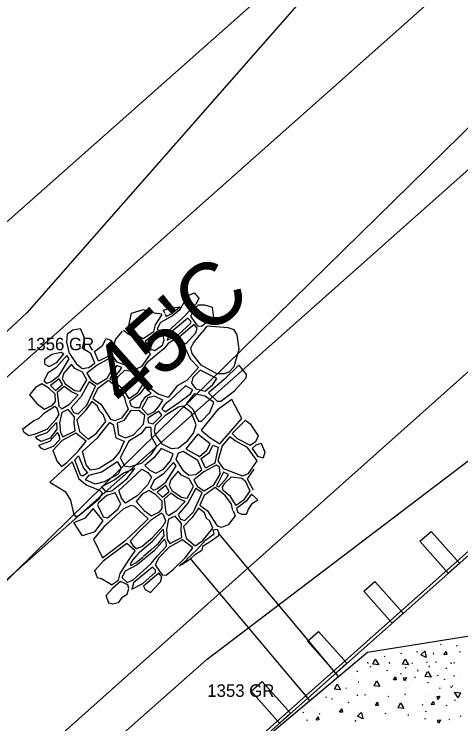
# Model space of a CAD drawing. Extents: x 49683 to 58852, y 49525 to 54803.
# Drawn here: x 53907.5 to 53943.1, y 51882.5 to 51939.1 of the extents above; entities that cross this region are included whole.
import ezdxf

# ---------------------------------------------------------------- set-up
doc = ezdxf.new("R2010")
doc.units = 0
for name, color, linetype in [('Level 1', 7, 'Continuous'), ('Level 11', 7, 'Continuous'), ('Level 16', 7, 'Continuous'), ('Level 18', 7, 'Continuous'), ('Level 27', 7, 'Continuous'), ('Level 3', 7, 'Continuous'), ('Level 48', 7, 'Continuous'), ('Level 57', 7, 'Continuous'), ('Level 7', 7, 'Continuous'), ('Level 8', 7, 'Continuous')]:
    doc.layers.add(name, color=color, linetype=linetype)

msp = doc.modelspace()

# ---------------------------------------------------------------- linework, layer by layer
at = {"layer": 'Level 1'}
msp.add_line((52544.807, 50683.302), (55534.583, 53340.862), dxfattribs=at)
at = {"layer": 'Level 11'}
msp.add_line((53894.91, 51911.927), (54324.203, 52292.615), dxfattribs=at)
at = {"layer": 'Level 16'}
for p, q in [((53922.709, 51897.172), (53923.403, 51897.677)), ((53923.325, 51897.993), (53923.656, 51898.041)), ((53923.403, 51897.677), (53923.325, 51897.993)), ((53923.656, 51898.041), (53923.782, 51897.709)), ((53923.782, 51897.709), (53923.735, 51897.472)), ((53922.014, 51896.397), (53922.709, 51897.172)), ((53923.277, 51897.172), (53922.882, 51896.903)), ((53923.735, 51897.472), (53923.277, 51897.172)), ((53922.488, 51896.65), (53922.409, 51896.334)), ((53922.882, 51896.903), (53922.488, 51896.65)), ((53921.225, 51895.639), (53922.014, 51896.397)), ((53921.84, 51895.97), (53921.351, 51895.544)), ((53922.409, 51896.334), (53921.84, 51895.97)), ((53920.609, 51895.117), (53921.272, 51895.623)), ((53921.351, 51895.544), (53920.861, 51895.212)), ((53921.272, 51895.623), (53921.225, 51895.639)), ((53920.861, 51895.212), (53920.609, 51895.117))]:
    msp.add_line(p, q, dxfattribs=at)
for points in [[(53920.663, 51915.527), (53921.297, 51916.644), (53921.805, 51916.891), (53922.188, 51916.466), (53921.968, 51915.993), (53920.907, 51914.878)], [(53919.463, 51915.272), (53919.414, 51915.368), (53919.357, 51915.487), (53919.785, 51915.644), (53920.688, 51915.777)], [(53919.463, 51915.243), (53919.525, 51915.115), (53919.574, 51914.993), (53919.979, 51915.201), (53920.688, 51915.777)], [(53920.649, 51915.752), (53920.58, 51915.692)], [(53922.152, 51915.935), (53921.818, 51915.582), (53921.515, 51915.034), (53921.872, 51914.52), (53922.084, 51914.241), (53922.397, 51914.219), (53922.734, 51914.491)], [(53922.152, 51915.935), (53922.639, 51915.912), (53923.236, 51915.727), (53923.335, 51915.11), (53923.376, 51914.761), (53923.165, 51914.529), (53922.734, 51914.491)], [(53916.531, 51913.893), (53916.806, 51915.251), (53917.767, 51915.561), (53918.262, 51915.334), (53919.236, 51915.208)], [(53916.531, 51913.893), (53917.759, 51913.251), (53918.605, 51913.803), (53918.74, 51914.33), (53919.256, 51915.166)], [(53920.663, 51915.527), (53920.089, 51915.042), (53919.133, 51914.527), (53918.875, 51914.024), (53919.291, 51913.632), (53919.769, 51913.841), (53920.907, 51914.878)], [(53911.864, 51912.039), (53911.674, 51912.978), (53911.719, 51913.601), (53912.149, 51913.935), (53912.737, 51914.029), (53913.058, 51913.271), (53912.88, 51912.467)], [(53922.489, 51913.783), (53922.845, 51914.23)], [(53924.393, 51910.513), (53924.597, 51910.588), (53925.009, 51911.007), (53925.398, 51912.39), (53925.238, 51913.545), (53924.997, 51913.943), (53924.52, 51914.087), (53922.845, 51914.23)], [(53916.074, 51913.829), (53915.541, 51913.187), (53915.185, 51911.998), (53915.613, 51911.374), (53917.156, 51910.812), (53917.634, 51910.996), (53918.333, 51911.99), (53917.563, 51913.055), (53916.559, 51913.593), (53916.187, 51913.876)], [(53924.393, 51910.513), (53924.214, 51910.427), (53923.626, 51910.427), (53922.367, 51911.118), (53921.654, 51912.041), (53921.539, 51912.492), (53921.771, 51912.933), (53922.473, 51913.768)], [(53920.982, 51912.658), (53920.442, 51913.07), (53920.087, 51913.057), (53919.731, 51912.849), (53919.388, 51912.407), (53918.039, 51911.303), (53917.523, 51910.567), (53918, 51909.672)], [(53911.864, 51912.039), (53912.403, 51911.248), (53912.88, 51910.844), (53913.419, 51910.918), (53913.897, 51911.274), (53913.58, 51912.033), (53912.88, 51912.467)], [(53921.008, 51912.632), (53921.496, 51911.61), (53922.146, 51910.939), (53921.243, 51909.909), (53920.455, 51909.457), (53919.729, 51908.543), (53918.932, 51908.794), (53918.449, 51909.171), (53918.026, 51909.646)], [(53909.896, 51911.196), (53909.897, 51911.601), (53910.461, 51911.997), (53911.207, 51912.149)], [(53909.896, 51911.196), (53910.256, 51911.009), (53910.868, 51911.325), (53911.434, 51912.022)], [(53911.207, 51912.149), (53911.434, 51912.022)], [(53924.191, 51909.973), (53925.358, 51911.106), (53925.948, 51910.362), (53925.923, 51910.069), (53925.029, 51909.06)], [(53908.684, 51908.742), (53909.309, 51908.027), (53909.889, 51907.604), (53910.526, 51907.928), (53910.761, 51908.208), (53910.74, 51908.789), (53910.238, 51909.291), (53909.679, 51909.626), (53909.154, 51909.346), (53908.684, 51908.742)], [(53916.383, 51908.049), (53916.283, 51908.544), (53915.782, 51909.242), (53914.974, 51909.878), (53914.103, 51909.228), (53913.747, 51908.456), (53914.371, 51908.003), (53915.134, 51906.813)], [(53924.191, 51909.973), (53922.963, 51908.904), (53923.655, 51908.254), (53923.949, 51908.254), (53925.029, 51909.06)], [(53910.078, 51905.997), (53910.816, 51906.811), (53911.04, 51907.191), (53910.895, 51907.649), (53910.694, 51907.828), (53909.811, 51907.235), (53909.448, 51906.89)], [(53916.398, 51908.022), (53916.56, 51907.616), (53916.022, 51906.889), (53915.484, 51906.688), (53915.161, 51906.784)], [(53910.078, 51905.997), (53909.064, 51905.575), (53908.631, 51905.491), (53908.248, 51905.781), (53908.147, 51906.03), (53909.002, 51906.664), (53909.448, 51906.89)], [(53924.849, 51905.67), (53925.892, 51906.732), (53926.271, 51906.43), (53926.922, 51905.469), (53926.688, 51905.003)], [(53910.092, 51905.74), (53910.838, 51906.543), (53910.871, 51906.018), (53910.325, 51905.303)], [(53910.325, 51905.303), (53909.605, 51905.031), (53909.339, 51905.178), (53909.158, 51905.41), (53910.092, 51905.74)], [(53910.584, 51904.628), (53911.104, 51905.181), (53911.071, 51905.482), (53910.926, 51905.739), (53910.303, 51905.048)], [(53911.242, 51903.031), (53911.65, 51903.36), (53912.578, 51904.266), (53913.205, 51905.049), (53912.378, 51905.696), (53911.294, 51905.103), (53910.547, 51904.314)], [(53924.849, 51905.67), (53925.242, 51905.277), (53926.27, 51904.739), (53926.708, 51905.025)], [(53910.584, 51904.628), (53909.874, 51904.359), (53909.608, 51904.506), (53909.426, 51904.738), (53910.303, 51905.048)], [(53926.755, 51904.751), (53926.429, 51904.482), (53926.87, 51903.87), (53927.315, 51903.734)], [(53926.755, 51904.751), (53927.157, 51904.882), (53927.438, 51904.183), (53927.315, 51903.734)], [(53910.547, 51904.314), (53910.882, 51903.436), (53911.242, 51903.031)], [(53912.079, 51903.394), (53910.308, 51901.775), (53911.528, 51901.045), (53911.943, 51900.353), (53912.184, 51899.292), (53912.36, 51899.052), (53912.636, 51899.124)], [(53912.079, 51903.394), (53912.623, 51902.058), (53913.244, 51901.542), (53914.255, 51901.143), (53914.466, 51900.932), (53914.244, 51900.416), (53912.636, 51899.124)], [(53926.569, 51902.818), (53926.035, 51902.056), (53926.511, 51901.161)], [(53924.894, 51899.538), (53924.795, 51900.033), (53924.293, 51900.731), (53923.485, 51901.367), (53922.615, 51900.717), (53922.259, 51899.944), (53922.883, 51899.492), (53923.645, 51898.302)], [(53916.412, 51897.203), (53917.103, 51897.839), (53918.143, 51898.857), (53917.072, 51899.839), (53916.759, 51899.928), (53916.156, 51899.637), (53915.017, 51898.597)], [(53913.883, 51897.836), (53914.553, 51898.691), (53913.757, 51899.697), (53913.108, 51898.916)], [(53924.909, 51899.511), (53925.072, 51899.105), (53924.533, 51898.377), (53923.996, 51898.176), (53923.672, 51898.273)], [(53913.883, 51897.836), (53912.915, 51897.5), (53912.222, 51898.58), (53913.108, 51898.916)], [(53915, 51898.581), (53914.628, 51898.262), (53913.794, 51897.232), (53914.503, 51895.762), (53916.394, 51897.186)], [(53917.442, 51896.191), (53918.477, 51897.092), (53919.349, 51898.032), (53919.382, 51897.507), (53918.879, 51896.847), (53918.353, 51896.366), (53917.763, 51895.851)], [(53918.354, 51895.28), (53918.9, 51895.909), (53919.616, 51896.669), (53919.583, 51896.971), (53919.438, 51897.227), (53918.621, 51896.322), (53917.898, 51895.735)], [(53915.213, 51893.588), (53915.788, 51893.963), (53915.923, 51894.49), (53916.672, 51895.703), (53917.101, 51896.304), (53916.44, 51896.892), (53914.545, 51895.478)], [(53917.417, 51896.166), (53916.904, 51895.569), (53916.708, 51895.275), (53916.757, 51895.152), (53917.161, 51895.361), (53917.744, 51895.834)], [(53915.213, 51893.588), (53914.421, 51894.081), (53914.118, 51894.153), (53913.895, 51894.75), (53914.545, 51895.478)], [(53917.873, 51895.71), (53917.271, 51895.202), (53916.315, 51894.686), (53916.057, 51894.183), (53916.473, 51893.792), (53916.951, 51894.001), (53918.328, 51895.255)], [(53918.335, 51892.985), (53919.12, 51893.844), (53919.231, 51894.224), (53918.986, 51894.518), (53917.784, 51893.487), (53917.906, 51893.218), (53918.335, 51892.985)], [(53916.056, 51892.577), (53916.472, 51892.861), (53916.595, 51893.302), (53916.534, 51893.608), (53915.947, 51893.853), (53915.324, 51893.338)], [(53916.056, 51892.577), (53915.757, 51892.172), (53915.312, 51892.066), (53915.008, 51892.138), (53914.786, 51892.735), (53915.324, 51893.338)]]:
    msp.add_lwpolyline(points, dxfattribs=at)
for points in [[(53921.302, 51914.86), (53919.805, 51913.608), (53919.67, 51913.106), (53920.54, 51913.536), (53921.558, 51914.456), (53921.546, 51914.615)], [(53921.803, 51914.358), (53920.601, 51913.328), (53920.724, 51913.058), (53921.152, 51912.826), (53921.937, 51913.684), (53922.048, 51914.064)], [(53917.918, 51912.994), (53918.358, 51912.382), (53918.677, 51912.284), (53919.29, 51912.701), (53919.413, 51913.142), (53919.352, 51913.449), (53918.764, 51913.693)], [(53914.794, 51913.247), (53915.223, 51913.089), (53914.939, 51911.802), (53914.192, 51911.421), (53913.862, 51912.193), (53914.512, 51912.671)], [(53911.659, 51911.873), (53910.82, 51910.923), (53910.138, 51910.486), (53909.825, 51909.86), (53910.059, 51909.671), (53910.383, 51909.794), (53911.043, 51910.297), (53911.86, 51911.606)], [(53913.259, 51909.95), (53912.904, 51910.55), (53912.292, 51910.843), (53912.023, 51911.186), (53911.434, 51910.475), (53911.299, 51910.046), (53911.519, 51909.629), (53912.29, 51909.103), (53912.731, 51909.03)], [(53915.049, 51911.643), (53914.081, 51911.115), (53913.259, 51910.489), (53913.565, 51909.938), (53914.092, 51909.608), (53914.876, 51910.074), (53915.379, 51910.945), (53915.307, 51911.484)], [(53915.625, 51911.092), (53915.084, 51909.989), (53915.268, 51909.928), (53915.869, 51910.627), (53916.041, 51910.921)], [(53917.73, 51909.6), (53917.239, 51908.864), (53916.639, 51908.435), (53916.198, 51909.145), (53915.623, 51909.622), (53915.562, 51909.903), (53915.746, 51910.21), (53916.274, 51910.713), (53917.094, 51910.604), (53917.351, 51910.396)], [(53923.626, 51910.049), (53922.283, 51910.719), (53921.715, 51910.13), (53921.589, 51909.668), (53921.956, 51909.217), (53922.69, 51909.05), (53923.3, 51909.576)], [(53911.043, 51910.029), (53910.349, 51909.492), (53910.762, 51909.102), (53911.31, 51909.56)], [(53913.433, 51909.786), (53912.806, 51908.624), (53912.012, 51907.718), (53912.202, 51907.349), (53912.559, 51907.238), (53913.252, 51907.931), (53913.947, 51909.452)], [(53911.444, 51909.426), (53910.896, 51908.945), (53911.029, 51907.851), (53911.264, 51907.639), (53911.901, 51908.03), (53912.572, 51908.746), (53912.025, 51908.98)], [(53917.872, 51909.349), (53917.441, 51908.792), (53916.664, 51908.204), (53916.779, 51907.878), (53917.094, 51907.732), (53917.482, 51907.743), (53917.619, 51908.131), (53917.955, 51908.614), (53918.376, 51908.888)], [(53921.704, 51909.154), (53921.127, 51909.479), (53919.908, 51908.323), (53919.435, 51907.955), (53919.246, 51907.64), (53919.497, 51907.388), (53920.59, 51908.124), (53921.514, 51908.818)], [(53919.32, 51908.322), (53918.659, 51908.647), (53918.123, 51908.51), (53917.639, 51907.669), (53918.122, 51907.166), (53918.657, 51907.429), (53919.004, 51907.818)], [(53923.371, 51908.138), (53922.69, 51908.63), (53921.798, 51908.829), (53921.198, 51908.062), (53921.702, 51907.601), (53922.152, 51906.646), (53922.383, 51906.646), (53923.066, 51907.329)], [(53924.804, 51908.364), (53923.664, 51907.542), (53922.376, 51905.936), (53923.049, 51905.336), (53923.869, 51904.835), (53925.611, 51906.87)], [(53913.644, 51908.211), (53913.129, 51907.473), (53912.458, 51906.757), (53912.669, 51905.83), (53913.372, 51905.217), (53913.987, 51905.653), (53914.782, 51906.626), (53914.548, 51907.173), (53914.258, 51907.463), (53914.113, 51907.854)], [(53920.904, 51907.852), (53920.558, 51907.778), (53919.486, 51907.084), (53918.709, 51906.306), (53918.614, 51905.855), (53918.739, 51905.54), (53919.221, 51904.847), (53919.987, 51904.46), (53920.554, 51904.524), (53921.311, 51905.112), (53921.763, 51905.69), (53921.963, 51906.352), (53921.586, 51907.317)], [(53911.777, 51907.572), (53911.263, 51907.348), (53911.083, 51906.521), (53911.161, 51905.75), (53911.35, 51905.404), (53912.323, 51905.886), (53912.256, 51906.467), (53912.279, 51907.003)], [(53916.739, 51907.48), (53916.201, 51906.71), (53915.674, 51906.498), (53915.778, 51905.55), (53916.336, 51905.329), (53916.979, 51905.572), (53917.771, 51906.406), (53917.866, 51907.112), (53917.403, 51907.491)], [(53919.004, 51907.44), (53918.121, 51906.893), (53918.142, 51906.536), (53918.53, 51906.442), (53919.224, 51907.136)], [(53915.084, 51906.54), (53915.357, 51906.371), (53915.577, 51905.307), (53916.241, 51905.045), (53915.85, 51904.19), (53915.312, 51903.526), (53914.194, 51902.85), (53913.551, 51902.733), (53913.193, 51903.155), (53912.91, 51904.24), (53914.123, 51905.348)], [(53917.95, 51906.142), (53917.549, 51905.636), (53916.61, 51905.055), (53915.902, 51903.716), (53916.249, 51903.074), (53916.681, 51903.001), (53917.662, 51903.328), (53918.4, 51904.004), (53918.823, 51904.658), (53918.423, 51905.395), (53918.382, 51906.154)], [(53922.106, 51905.617), (53921.137, 51904.452), (53922.239, 51903.84), (53922.827, 51904.331), (53923.073, 51904.846)], [(53926.845, 51903.478), (53926.074, 51904.543), (53925.07, 51905.081), (53924.654, 51905.399), (53924.053, 51904.676), (53923.696, 51903.487), (53924.124, 51902.862), (53925.667, 51902.3), (53926.145, 51902.485)], [(53919.181, 51904.468), (53918.59, 51903.73), (53917.883, 51903.107), (53918.283, 51902.749), (53918.767, 51902.497), (53919.379, 51902.814), (53919.928, 51903.489), (53920.15, 51904.048)], [(53923.305, 51904.736), (53923.734, 51904.577), (53923.451, 51903.29), (53922.703, 51902.91), (53922.373, 51903.681), (53923.023, 51904.16)], [(53912.604, 51903.892), (53912.982, 51902.901), (53913.319, 51902.522), (53912.95, 51902.258), (53912.739, 51902.343), (53912.298, 51903.565)], [(53922.409, 51902.762), (53922.091, 51903.522), (53920.928, 51904.243), (53920.536, 51904.096), (53920.339, 51903.581), (53920.914, 51902.736), (53921.391, 51902.332), (53921.931, 51902.406)], [(53915.681, 51903.431), (53915.986, 51902.894), (53915.753, 51902.43), (53914.636, 51901.818), (53913.908, 51901.617), (53913.15, 51901.974), (53913.445, 51902.333), (53914.447, 51902.619)], [(53920.171, 51903.362), (53919.332, 51902.411), (53918.65, 51901.975), (53918.336, 51901.349), (53918.571, 51901.159), (53918.895, 51901.282), (53919.555, 51901.786), (53920.372, 51903.094)], [(53917.092, 51902.864), (53916.185, 51902.505), (53915.479, 51901.966), (53914.414, 51901.407), (53914.772, 51901.006), (53915.256, 51901.091), (53916.438, 51902.041)], [(53917.63, 51902.812), (53918.125, 51902.549), (53918.419, 51902.191), (53918.081, 51901.558), (53917.258, 51900.693), (53916.351, 51900.123), (53916.025, 51900.513), (53915.815, 51901.124), (53916.786, 51902.031)], [(53923.561, 51903.131), (53922.592, 51902.603), (53921.771, 51901.977), (53922.077, 51901.427), (53922.603, 51901.096), (53923.388, 51901.563), (53923.891, 51902.433), (53923.818, 51902.972)], [(53921.77, 51901.438), (53921.416, 51902.038), (53920.803, 51902.332), (53920.534, 51902.674), (53919.945, 51901.963), (53919.81, 51901.534), (53920.03, 51901.118), (53920.801, 51900.592), (53921.242, 51900.519)], [(53924.136, 51902.581), (53923.596, 51901.477), (53923.78, 51901.416), (53924.381, 51902.115), (53924.553, 51902.409)], [(53926.242, 51901.088), (53925.751, 51900.353), (53925.15, 51899.923), (53924.71, 51900.633), (53924.134, 51901.11), (53924.074, 51901.392), (53924.258, 51901.699), (53924.785, 51902.201), (53925.606, 51902.092), (53925.863, 51901.884)], [(53919.273, 51899.696), (53919.251, 51900.277), (53918.749, 51900.78), (53918.191, 51901.114), (53917.665, 51900.834), (53917.195, 51900.23), (53917.82, 51899.516), (53918.401, 51899.092), (53919.038, 51899.417)], [(53919.554, 51901.518), (53918.861, 51900.981), (53919.274, 51900.59), (53919.822, 51901.049)], [(53921.945, 51901.275), (53921.318, 51900.112), (53920.524, 51899.206), (53920.713, 51898.838), (53921.07, 51898.726), (53921.764, 51899.42), (53922.458, 51900.94)], [(53915.509, 51900.944), (53914.856, 51900.733), (53914.191, 51900.131), (53914.106, 51899.983), (53914.569, 51899.014), (53914.906, 51898.931), (53915.719, 51899.638), (53915.961, 51900.07)], [(53919.956, 51900.915), (53919.408, 51900.434), (53919.541, 51899.339), (53919.775, 51899.127), (53920.412, 51899.519), (53921.083, 51900.235), (53920.536, 51900.469)], [(53926.384, 51900.838), (53925.953, 51900.281), (53925.175, 51899.692), (53925.29, 51899.367), (53925.605, 51899.22), (53925.994, 51899.231), (53926.13, 51899.62), (53926.467, 51900.103), (53926.887, 51900.376)], [(53919.205, 51899.316), (53918.322, 51898.723), (53917.416, 51897.862), (53916.711, 51897.09), (53916.923, 51896.744), (53917.225, 51896.488), (53917.638, 51896.656), (53918.477, 51897.36), (53919.327, 51898.3), (53919.551, 51898.68), (53919.406, 51899.138)], [(53922.155, 51899.7), (53921.641, 51898.962), (53920.969, 51898.246), (53921.181, 51897.319), (53921.884, 51896.705), (53922.499, 51897.142), (53923.293, 51898.114), (53923.059, 51898.662), (53922.769, 51898.952), (53922.624, 51899.343)], [(53920.289, 51899.061), (53919.775, 51898.837), (53919.595, 51898.01), (53919.672, 51897.239), (53919.862, 51896.893), (53920.834, 51897.374), (53920.768, 51897.955), (53920.791, 51898.492)], [(53921.716, 51896.537), (53920.89, 51897.184), (53919.806, 51896.591), (53919, 51895.741), (53918.698, 51895.193), (53919.055, 51894.68), (53919.267, 51894.401), (53919.58, 51894.379), (53920.161, 51894.849), (53921.089, 51895.755)], [(53918.484, 51895.019), (53916.988, 51893.768), (53916.853, 51893.265), (53917.723, 51893.695), (53918.741, 51894.615), (53918.729, 51894.775)]]:
    msp.add_lwpolyline(points, close=True, dxfattribs=at)
at = {"layer": 'Level 18'}
for p, q in [((53921.658, 51908.457), (53948.816, 51935.102)), ((53890.152, 51877.545), (53921.658, 51908.457))]:
    msp.add_line(p, q, dxfattribs=at)
at = {"layer": 'Level 27'}
for p, q in [((53923.963, 51878.77), (53966.012, 51916.147)), ((53924.129, 51878.584), (53966.178, 51915.961)), ((53939.808, 51897.07), (53940.692, 51897.855)), ((53940.692, 51897.855), (53942.95, 51895.313)), ((53942.067, 51894.528), (53939.808, 51897.07)), ((53942.95, 51895.313), (53942.067, 51894.528)), ((53935.324, 51893.084), (53936.207, 51893.869)), ((53936.207, 51893.869), (53938.466, 51891.327)), ((53937.582, 51890.542), (53935.324, 51893.084)), ((53938.466, 51891.327), (53937.582, 51890.542)), ((53930.839, 51889.098), (53931.723, 51889.883)), ((53931.723, 51889.883), (53933.981, 51887.341)), ((53933.098, 51886.556), (53930.839, 51889.098)), ((53933.981, 51887.341), (53933.098, 51886.556)), ((53926.355, 51885.111), (53927.238, 51885.896)), ((53927.238, 51885.896), (53929.497, 51883.355)), ((53928.613, 51882.57), (53926.355, 51885.111)), ((53929.497, 51883.355), (53928.613, 51882.57))]:
    msp.add_line(p, q, dxfattribs=at)
at = {"layer": 'Level 3'}
for p, q in [((53883.273, 51889.178), (54069.537, 52054.718)), ((53898.742, 51870.567), (54083.389, 52035.124))]:
    msp.add_line(p, q, dxfattribs=at)
at = {"layer": 'Level 7'}
for p, q in [((53934.082, 51944.47), (53908.487, 51915.299)), ((53908.487, 51915.299), (53883.022, 51891.572)), ((53922.854, 51887.665), (53958.852, 51915.059)), ((53902.065, 51869.327), (53922.854, 51887.665))]:
    msp.add_line(p, q, dxfattribs=at)
at = {"layer": 'Level 8'}
for p, q in [((53933.325, 51886.292), (53923.765, 51897.699)), ((53931.026, 51884.365), (53921.496, 51895.735)), ((53935.625, 51888.219), (53953.195, 51891.04)), ((53941.504, 51888.801), (53941.444, 51888.86)), ((53942.79, 51888.71), (53942.726, 51888.729)), ((53924.129, 51878.584), (53935.625, 51888.219)), ((53938.29, 51888.175), (53938.314, 51888.087)), ((53939.549, 51888.32), (53939.573, 51888.232)), ((53940.867, 51888.166), (53940.892, 51888.078)), ((53942.951, 51888.305), (53942.976, 51888.217)), ((53935.631, 51887.423), (53935.655, 51887.336)), ((53937.045, 51887.867), (53936.981, 51887.886)), ((53937.348, 51887.426), (53937.372, 51887.338)), ((53940.317, 51887.485), (53940.341, 51887.397)), ((53941.074, 51887.495), (53941.098, 51887.407)), ((53942.501, 51887.431), (53942.525, 51887.343)), ((53935.843, 51887.113), (53935.867, 51887.025)), ((53938.643, 51887.037), (53938.667, 51886.949)), ((53939.216, 51887.291), (53939.189, 51887.378)), ((53940.557, 51887.039), (53940.53, 51887.126)), ((53941.883, 51886.976), (53941.907, 51886.888)), ((53942.271, 51887.397), (53942.296, 51887.309)), ((53934.789, 51886.743), (53934.813, 51886.655)), ((53937.175, 51886.819), (53937.199, 51886.731)), ((53938.254, 51886.551), (53938.278, 51886.463)), ((53939.614, 51886.81), (53939.638, 51886.723)), ((53941.2, 51886.422), (53941.224, 51886.334)), ((53942.498, 51886.393), (53942.522, 51886.305)), ((53942.977, 51886.338), (53942.977, 51886.338)), ((53934.374, 51886.047), (53934.374, 51886.047)), ((53934.503, 51886.153), (53934.503, 51886.153)), ((53934.939, 51885.83), (53934.875, 51885.849)), ((53939.379, 51886.247), (53939.443, 51886.23)), ((53940.456, 51885.749), (53940.429, 51885.836)), ((53941.716, 51886.066), (53941.781, 51886.048)), ((53933.956, 51885.326), (53933.892, 51885.346)), ((53938.859, 51885.404), (53938.859, 51885.404)), ((53941.362, 51885.417), (53941.386, 51885.329)), ((53942.268, 51885.482), (53942.293, 51885.394)), ((53942.43, 51885.512), (53942.366, 51885.531)), ((53932.296, 51884.701), (53932.321, 51884.614)), ((53934.79, 51884.834), (53934.814, 51884.746)), ((53935.412, 51884.878), (53935.437, 51884.79)), ((53937.327, 51884.668), (53937.263, 51884.688)), ((53938.596, 51884.945), (53938.62, 51884.858)), ((53940.603, 51884.837), (53940.603, 51884.837)), ((53941.228, 51884.758), (53941.252, 51884.67)), ((53932.754, 51884.572), (53932.778, 51884.484)), ((53934.086, 51884.278), (53934.11, 51884.19)), ((53940.056, 51884.011), (53939.992, 51884.03)), ((53942.56, 51884.464), (53942.584, 51884.376)), ((53930.483, 51883.47), (53930.508, 51883.382)), ((53931.285, 51883.506), (53931.285, 51883.506)), ((53931.413, 51883.612), (53931.413, 51883.612)), ((53940.324, 51883.475), (53940.26, 51883.494)), ((53941.936, 51883.921), (53941.909, 51884.008)), ((53931.85, 51883.289), (53931.786, 51883.309)), ((53937.038, 51883.389), (53937.062, 51883.301)), ((53938.854, 51883.257), (53938.878, 51883.169)), ((53940.186, 51882.963), (53940.21, 51882.875)), ((53943.013, 51883.181), (53943.037, 51883.093)), ((53930.867, 51882.786), (53930.803, 51882.805)), ((53934.632, 51882.801), (53934.656, 51882.713)), ((53942.098, 51882.877), (53942.163, 51882.86))]:
    msp.add_line(p, q, dxfattribs=at)
for points in [[(53940.189, 51888.324), (53940.296, 51887.801), (53939.87, 51888.013), (53940.182, 51888.318)], [(53941.887, 51888.279), (53941.948, 51888.03), (53941.717, 51888.019), (53941.887, 51888.279)], [(53936.245, 51887.669), (53936.524, 51887.214), (53936.051, 51887.268), (53936.24, 51887.661)], [(53938.619, 51887.679), (53938.898, 51887.224), (53938.425, 51887.278), (53938.614, 51887.671)], [(53940.421, 51886.696), (53940.7, 51886.242), (53940.227, 51886.295), (53940.417, 51886.688)], [(53936.342, 51885.951), (53936.621, 51885.496), (53936.148, 51885.55), (53936.337, 51885.943)], [(53937.86, 51886.274), (53937.921, 51886.025), (53937.69, 51886.015), (53937.86, 51886.274)], [(53938.563, 51885.931), (53938.494, 51886.178), (53938.725, 51886.196), (53938.563, 51885.931)], [(53933.202, 51885.692), (53933.481, 51885.237), (53933.008, 51885.291), (53933.197, 51885.684)], [(53941.234, 51884.444), (53941.165, 51884.691), (53941.395, 51884.708), (53941.234, 51884.444)], [(53942.845, 51884.591), (53942.552, 51885.037), (53943.026, 51884.998), (53942.849, 51884.599)], [(53936.424, 51884.237), (53936.485, 51883.988), (53936.254, 51883.978), (53936.424, 51884.237)], [(53938.252, 51884.201), (53938.531, 51883.746), (53938.058, 51883.8), (53938.247, 51884.193)], [(53940.881, 51884.301), (53940.942, 51884.052), (53940.711, 51884.042), (53940.881, 51884.301)], [(53933.569, 51883.706), (53933.63, 51883.457), (53933.399, 51883.447), (53933.569, 51883.706)], [(53931.692, 51883.076), (53931.753, 51882.827), (53931.522, 51882.816), (53931.692, 51883.076)], [(53935.139, 51883.43), (53935.246, 51882.908), (53934.82, 51883.12), (53935.132, 51883.425)], [(53941.283, 51882.561), (53941.214, 51882.808), (53941.444, 51882.826), (53941.283, 51882.561)]]:
    msp.add_lwpolyline(points, dxfattribs=at)

# ---------------------------------------------------------------- texts
at = {"layer": 'Level 48'}
msp.add_text("45'C", height=5, rotation=41.6334, dxfattribs=at).set_placement((53916.403, 51907.455))
at = {"layer": 'Level 57'}
for s, p in [('1356 GR', (53908.487, 51912.299)), ('1353 GR', (53922.854, 51884.665))]:
    msp.add_text(s, height=1, dxfattribs=at).set_placement(p)

doc.saveas('drawing.dxf')
